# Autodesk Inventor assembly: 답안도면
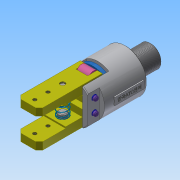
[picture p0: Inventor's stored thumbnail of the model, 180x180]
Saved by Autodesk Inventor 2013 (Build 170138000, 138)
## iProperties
Created: 2019-02
Part Number: 답안도면
Document SubType Name: Assembly
Designer: Administrator
Author: Administrator
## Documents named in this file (11)
- C:\Users\Administrator\Desktop\490207V1005\답안도면.iam
- C:\Users\Administrator\Desktop\490207V1005\본체.ipt
- C:\Users\Administrator\Desktop\490207V1005\E-링.ipt
- C:\Users\Administrator\Desktop\490207V1005\O-링.ipt
- C:\Users\Administrator\Desktop\490207V1005\가이드핀.ipt
- C:\Users\Administrator\Desktop\490207V1005\부시.ipt
- C:\Users\Administrator\Desktop\490207V1005\스프링.ipt
- C:\Users\Administrator\Desktop\490207V1005\평행핀 6x28.ipt
- C:\Users\Administrator\Desktop\490207V1005\피스톤.ipt
- C:\Users\Administrator\Desktop\490207V1005\핀.ipt
- C:\Users\Administrator\Desktop\490207V1005\핑거.ipt
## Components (11 placed, 6 different names)
1. E-링:1
2. O-링:1 — 각도:1, 각도:2
3. 가이드핀:1
4. 피스톤:1
5. 핀:1
6. 핑거:1
7. 핑거:2 — 플러쉬:2
8. O-링:2
9. 핀:2
10. E-링:2
11. 가이드핀:2
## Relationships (3: Angle 2, Flush 1)
- 각도:1 [Angle]: O-링:1
- 각도:2 [Angle]: O-링:1
- 플러쉬:2 [Flush]: 핑거:2
